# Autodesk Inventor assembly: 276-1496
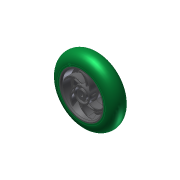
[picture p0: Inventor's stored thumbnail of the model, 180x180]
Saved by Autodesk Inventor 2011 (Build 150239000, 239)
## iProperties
Company: Autodesk Inc.
Created: 2010-06
Part Number: 276-1496
Document SubType Name: Assembly
Designer: Autodesk Inc.
Catalog Web Link: http://www.vexrobotics.com/products/accessories/motion/276-1496.html
Vendor: Innovation First, Inc.
Author: Autodesk Inc.
Title: VEX Robotics Kit of Parts
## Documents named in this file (3)
- D:\@VEX\BZ-Parts Kit\Motion\Small Wheel.iam
- D:\@VEX\BZ-Parts Kit\Motion\Small Wheel Hub.ipt
- D:\@VEX\BZ-Parts Kit\Motion\Small Wheel Tire.ipt
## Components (2 placed, 2 different names)
1. Small Wheel Hub:1 — Flush:1, Mate:1, Angle:1
2. Small Wheel Tire:1 — Flush:1, Mate:1, Angle:1
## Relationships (3: Flush 1, Mate 1, Angle 1)
- Flush:1: Small Wheel Hub:1 ↔ Small Wheel Tire:1
- Mate:1: Small Wheel Hub:1 ↔ Small Wheel Tire:1
- Angle:1: Small Wheel Hub:1 ↔ Small Wheel Tire:1
